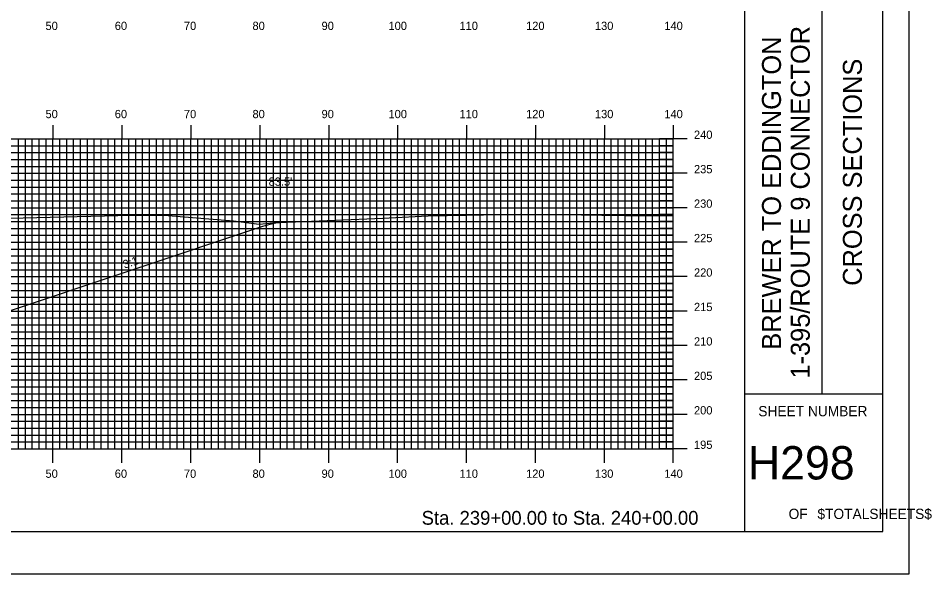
# Model space of a CAD drawing. Extents: x 1801536 to 1801879, y 442591 to 442811.
# Drawn here: x 1801746.5 to 1801879.1, y 442590.5 to 442671.2 of the extents above; entities that cross this region are included whole.
import ezdxf

# ---------------------------------------------------------------- set-up
doc = ezdxf.new("R2010")
doc.units = 0
for name, color, linetype in [('ANNOTATION', 7, 'Continuous'), ('BORDER', 7, 'Continuous'), ('D_Roadway_SlopeLines', 7, 'Continuous'), ('D_Text_Standard', 7, 'Continuous'), ('H_V ANNOTATION', 7, 'Continuous'), ('M_Roadway_Centerline', 7, 'Continuous'), ('MAJOR', 7, 'Continuous'), ('MINOR', 7, 'Continuous'), ('PLOT BOUNDARY', 7, 'Continuous'), ('S_Roadway_Centerline', 7, 'Continuous')]:
    doc.layers.add(name, color=color, linetype=linetype)

msp = doc.modelspace()

# ---------------------------------------------------------------- linework, layer by layer
at = {"layer": 'BORDER'}
for p, q in [((1801851.98, 442596.67), (1801851.98, 442806.67)), ((1801863.16, 442616.67), (1801863.16, 442686.67)), ((1801851.98, 442616.67), (1801871.98, 442616.67))]:
    msp.add_line(p, q, dxfattribs=at)
msp.add_lwpolyline([(1801551.98, 442596.67), (1801871.98, 442596.67), (1801871.98, 442806.67), (1801551.98, 442806.67)], close=True, dxfattribs=at)
at = {"layer": 'D_Roadway_SlopeLines'}
msp.add_line((1801781.97, 442640.93), (1801744.36, 442628.39), dxfattribs=at)
msp.add_arc((1801786.17, 442628.31), 13.3, 94.7119, 108.4349, dxfattribs=at)
at = {"layer": 'MAJOR'}
for p, q in [((1801751.58, 442655.67), (1801751.58, 442653.67)), ((1801761.58, 442655.67), (1801761.58, 442653.67)), ((1801771.58, 442655.67), (1801771.58, 442653.67)), ((1801781.58, 442655.67), (1801781.58, 442653.67)), ((1801791.58, 442655.67), (1801791.58, 442653.67)), ((1801801.58, 442655.67), (1801801.58, 442653.67)), ((1801811.58, 442655.67), (1801811.58, 442653.67)), ((1801821.58, 442655.67), (1801821.58, 442653.67)), ((1801831.58, 442655.67), (1801831.58, 442653.67)), ((1801841.58, 442655.67), (1801841.58, 442653.67)), ((1801561.58, 442653.67), (1801841.58, 442653.67)), ((1801561.58, 442653.67), (1801841.58, 442653.67)), ((1801751.58, 442608.67), (1801751.58, 442653.67)), ((1801761.58, 442608.67), (1801761.58, 442653.67)), ((1801771.58, 442608.67), (1801771.58, 442653.67)), ((1801781.58, 442608.67), (1801781.58, 442653.67)), ((1801791.58, 442608.67), (1801791.58, 442653.67)), ((1801801.58, 442608.67), (1801801.58, 442653.67)), ((1801811.58, 442608.67), (1801811.58, 442653.67)), ((1801821.58, 442608.67), (1801821.58, 442653.67)), ((1801831.58, 442608.67), (1801831.58, 442653.67)), ((1801843.58, 442653.67), (1801839.57, 442653.67)), ((1801841.58, 442608.67), (1801841.58, 442653.67)), ((1801841.58, 442608.67), (1801841.58, 442653.67)), ((1801561.58, 442648.67), (1801841.58, 442648.67)), ((1801843.58, 442648.67), (1801839.57, 442648.67)), ((1801561.58, 442643.67), (1801841.58, 442643.67)), ((1801843.58, 442643.67), (1801839.57, 442643.67)), ((1801561.58, 442638.67), (1801841.58, 442638.67)), ((1801843.58, 442638.67), (1801839.57, 442638.67)), ((1801561.58, 442633.67), (1801841.58, 442633.67)), ((1801843.58, 442633.67), (1801839.57, 442633.67)), ((1801561.58, 442628.67), (1801841.58, 442628.67)), ((1801843.58, 442628.67), (1801839.57, 442628.67)), ((1801561.58, 442623.67), (1801841.58, 442623.67)), ((1801843.58, 442623.67), (1801839.57, 442623.67)), ((1801561.58, 442618.67), (1801841.58, 442618.67)), ((1801843.58, 442618.67), (1801839.57, 442618.67)), ((1801561.58, 442613.67), (1801841.58, 442613.67)), ((1801843.58, 442613.67), (1801839.57, 442613.67)), ((1801561.58, 442608.67), (1801841.58, 442608.67)), ((1801561.58, 442608.67), (1801841.58, 442608.67)), ((1801751.58, 442606.66), (1801751.58, 442608.67)), ((1801761.58, 442606.66), (1801761.58, 442608.67)), ((1801771.58, 442606.66), (1801771.58, 442608.67)), ((1801781.58, 442606.66), (1801781.58, 442608.67)), ((1801791.58, 442606.66), (1801791.58, 442608.67)), ((1801801.58, 442606.66), (1801801.58, 442608.67)), ((1801811.58, 442606.66), (1801811.58, 442608.67)), ((1801821.58, 442606.66), (1801821.58, 442608.67)), ((1801831.58, 442606.66), (1801831.58, 442608.67)), ((1801843.58, 442608.67), (1801839.57, 442608.67)), ((1801841.58, 442606.66), (1801841.58, 442608.67))]:
    msp.add_line(p, q, dxfattribs=at)
at = {"layer": 'MINOR'}
for p, q in [((1801561.58, 442652.67), (1801841.58, 442652.67)), ((1801746.58, 442608.67), (1801746.58, 442653.67)), ((1801747.58, 442608.67), (1801747.58, 442653.67)), ((1801748.58, 442608.67), (1801748.58, 442653.67)), ((1801749.58, 442608.67), (1801749.58, 442653.67)), ((1801750.58, 442608.67), (1801750.58, 442653.67)), ((1801752.58, 442608.67), (1801752.58, 442653.67)), ((1801753.58, 442608.67), (1801753.58, 442653.67)), ((1801754.58, 442608.67), (1801754.58, 442653.67)), ((1801755.58, 442608.67), (1801755.58, 442653.67)), ((1801756.58, 442608.67), (1801756.58, 442653.67)), ((1801757.58, 442608.67), (1801757.58, 442653.67)), ((1801758.58, 442608.67), (1801758.58, 442653.67)), ((1801759.58, 442608.67), (1801759.58, 442653.67)), ((1801760.58, 442608.67), (1801760.58, 442653.67)), ((1801762.58, 442608.67), (1801762.58, 442653.67)), ((1801763.58, 442608.67), (1801763.58, 442653.67)), ((1801764.58, 442608.67), (1801764.58, 442653.67)), ((1801765.58, 442608.67), (1801765.58, 442653.67)), ((1801766.58, 442608.67), (1801766.58, 442653.67)), ((1801767.58, 442608.67), (1801767.58, 442653.67)), ((1801768.58, 442608.67), (1801768.58, 442653.67)), ((1801769.58, 442608.67), (1801769.58, 442653.67)), ((1801770.58, 442608.67), (1801770.58, 442653.67)), ((1801772.58, 442608.67), (1801772.58, 442653.67)), ((1801773.58, 442608.67), (1801773.58, 442653.67)), ((1801774.58, 442608.67), (1801774.58, 442653.67)), ((1801775.58, 442608.67), (1801775.58, 442653.67)), ((1801776.58, 442608.67), (1801776.58, 442653.67)), ((1801777.58, 442608.67), (1801777.58, 442653.67)), ((1801778.58, 442608.67), (1801778.58, 442653.67)), ((1801779.58, 442608.67), (1801779.58, 442653.67)), ((1801780.58, 442608.67), (1801780.58, 442653.67)), ((1801782.58, 442608.67), (1801782.58, 442653.67)), ((1801783.58, 442608.67), (1801783.58, 442653.67)), ((1801784.58, 442608.67), (1801784.58, 442653.67)), ((1801785.58, 442608.67), (1801785.58, 442653.67)), ((1801786.58, 442608.67), (1801786.58, 442653.67)), ((1801787.58, 442608.67), (1801787.58, 442653.67)), ((1801788.58, 442608.67), (1801788.58, 442653.67)), ((1801789.58, 442608.67), (1801789.58, 442653.67)), ((1801790.58, 442608.67), (1801790.58, 442653.67)), ((1801792.58, 442608.67), (1801792.58, 442653.67)), ((1801793.58, 442608.67), (1801793.58, 442653.67)), ((1801794.58, 442608.67), (1801794.58, 442653.67)), ((1801795.58, 442608.67), (1801795.58, 442653.67)), ((1801796.58, 442608.67), (1801796.58, 442653.67)), ((1801797.58, 442608.67), (1801797.58, 442653.67)), ((1801798.58, 442608.67), (1801798.58, 442653.67)), ((1801799.58, 442608.67), (1801799.58, 442653.67)), ((1801800.58, 442608.67), (1801800.58, 442653.67)), ((1801802.58, 442608.67), (1801802.58, 442653.67)), ((1801803.58, 442608.67), (1801803.58, 442653.67)), ((1801804.58, 442608.67), (1801804.58, 442653.67)), ((1801805.58, 442608.67), (1801805.58, 442653.67)), ((1801806.58, 442608.67), (1801806.58, 442653.67)), ((1801807.58, 442608.67), (1801807.58, 442653.67)), ((1801808.58, 442608.67), (1801808.58, 442653.67)), ((1801809.58, 442608.67), (1801809.58, 442653.67)), ((1801810.58, 442608.67), (1801810.58, 442653.67)), ((1801812.58, 442608.67), (1801812.58, 442653.67)), ((1801813.58, 442608.67), (1801813.58, 442653.67)), ((1801814.58, 442608.67), (1801814.58, 442653.67)), ((1801815.58, 442608.67), (1801815.58, 442653.67)), ((1801816.58, 442608.67), (1801816.58, 442653.67)), ((1801817.58, 442608.67), (1801817.58, 442653.67)), ((1801818.58, 442608.67), (1801818.58, 442653.67)), ((1801819.58, 442608.67), (1801819.58, 442653.67)), ((1801820.58, 442608.67), (1801820.58, 442653.67)), ((1801822.58, 442608.67), (1801822.58, 442653.67)), ((1801823.58, 442608.67), (1801823.58, 442653.67)), ((1801824.58, 442608.67), (1801824.58, 442653.67)), ((1801825.58, 442608.67), (1801825.58, 442653.67)), ((1801826.58, 442608.67), (1801826.58, 442653.67)), ((1801827.58, 442608.67), (1801827.58, 442653.67)), ((1801828.58, 442608.67), (1801828.58, 442653.67)), ((1801829.58, 442608.67), (1801829.58, 442653.67)), ((1801830.58, 442608.67), (1801830.58, 442653.67)), ((1801832.58, 442608.67), (1801832.58, 442653.67)), ((1801833.58, 442608.67), (1801833.58, 442653.67)), ((1801834.58, 442608.67), (1801834.58, 442653.67)), ((1801835.58, 442608.67), (1801835.58, 442653.67)), ((1801836.58, 442608.67), (1801836.58, 442653.67)), ((1801837.58, 442608.67), (1801837.58, 442653.67)), ((1801838.58, 442608.67), (1801838.58, 442653.67)), ((1801841.58, 442652.67), (1801839.57, 442652.67)), ((1801839.58, 442608.67), (1801839.58, 442653.67)), ((1801840.58, 442608.67), (1801840.58, 442653.67)), ((1801561.58, 442651.67), (1801841.58, 442651.67)), ((1801841.58, 442651.67), (1801839.57, 442651.67)), ((1801561.58, 442650.67), (1801841.58, 442650.67)), ((1801841.58, 442650.67), (1801839.57, 442650.67)), ((1801561.58, 442649.67), (1801841.58, 442649.67)), ((1801841.58, 442649.67), (1801839.57, 442649.67)), ((1801561.58, 442647.67), (1801841.58, 442647.67)), ((1801841.58, 442647.67), (1801839.57, 442647.67)), ((1801561.58, 442646.67), (1801841.58, 442646.67)), ((1801841.58, 442646.67), (1801839.57, 442646.67)), ((1801561.58, 442645.67), (1801841.58, 442645.67)), ((1801841.58, 442645.67), (1801839.57, 442645.67)), ((1801561.58, 442644.67), (1801841.58, 442644.67)), ((1801841.58, 442644.67), (1801839.57, 442644.67)), ((1801561.58, 442642.67), (1801841.58, 442642.67)), ((1801841.58, 442642.67), (1801839.57, 442642.67)), ((1801561.58, 442641.67), (1801841.58, 442641.67)), ((1801841.58, 442641.67), (1801839.57, 442641.67)), ((1801561.58, 442640.67), (1801841.58, 442640.67)), ((1801561.58, 442639.67), (1801841.58, 442639.67)), ((1801841.58, 442640.67), (1801839.57, 442640.67)), ((1801841.58, 442639.67), (1801839.57, 442639.67)), ((1801561.58, 442637.67), (1801841.58, 442637.67)), ((1801841.58, 442637.67), (1801839.57, 442637.67)), ((1801561.58, 442636.67), (1801841.58, 442636.67)), ((1801561.58, 442635.67), (1801841.58, 442635.67)), ((1801841.58, 442636.67), (1801839.57, 442636.67)), ((1801841.58, 442635.67), (1801839.57, 442635.67)), ((1801561.58, 442634.67), (1801841.58, 442634.67)), ((1801841.58, 442634.67), (1801839.57, 442634.67)), ((1801561.58, 442632.67), (1801841.58, 442632.67)), ((1801561.58, 442631.67), (1801841.58, 442631.67)), ((1801841.58, 442632.67), (1801839.57, 442632.67)), ((1801841.58, 442631.67), (1801839.57, 442631.67)), ((1801561.58, 442630.67), (1801841.58, 442630.67)), ((1801841.58, 442630.67), (1801839.57, 442630.67)), ((1801561.58, 442629.67), (1801841.58, 442629.67)), ((1801841.58, 442629.67), (1801839.57, 442629.67)), ((1801561.58, 442627.67), (1801841.58, 442627.67)), ((1801841.58, 442627.67), (1801839.57, 442627.67)), ((1801561.58, 442626.67), (1801841.58, 442626.67)), ((1801841.58, 442626.67), (1801839.57, 442626.67)), ((1801561.58, 442625.67), (1801841.58, 442625.67)), ((1801841.58, 442625.67), (1801839.57, 442625.67)), ((1801561.58, 442624.67), (1801841.58, 442624.67)), ((1801841.58, 442624.67), (1801839.57, 442624.67)), ((1801561.58, 442622.67), (1801841.58, 442622.67)), ((1801841.58, 442622.67), (1801839.57, 442622.67)), ((1801561.58, 442621.67), (1801841.58, 442621.67)), ((1801841.58, 442621.67), (1801839.57, 442621.67)), ((1801561.58, 442620.67), (1801841.58, 442620.67)), ((1801561.58, 442619.67), (1801841.58, 442619.67)), ((1801841.58, 442620.67), (1801839.57, 442620.67)), ((1801841.58, 442619.67), (1801839.57, 442619.67)), ((1801561.58, 442617.67), (1801841.58, 442617.67)), ((1801841.58, 442617.67), (1801839.57, 442617.67)), ((1801561.58, 442616.67), (1801841.58, 442616.67)), ((1801561.58, 442615.67), (1801841.58, 442615.67)), ((1801841.58, 442616.67), (1801839.57, 442616.67)), ((1801841.58, 442615.67), (1801839.57, 442615.67)), ((1801561.58, 442614.67), (1801841.58, 442614.67)), ((1801841.58, 442614.67), (1801839.57, 442614.67)), ((1801561.58, 442612.67), (1801841.58, 442612.67)), ((1801561.58, 442611.67), (1801841.58, 442611.67)), ((1801841.58, 442612.67), (1801839.57, 442612.67)), ((1801841.58, 442611.67), (1801839.57, 442611.67)), ((1801561.58, 442610.67), (1801841.58, 442610.67)), ((1801841.58, 442610.67), (1801839.57, 442610.67)), ((1801561.58, 442609.67), (1801841.58, 442609.67)), ((1801841.58, 442609.67), (1801839.57, 442609.67))]:
    msp.add_line(p, q, dxfattribs=at)
at = {"layer": 'PLOT BOUNDARY'}
msp.add_lwpolyline([(1801535.79, 442590.55), (1801875.79, 442590.55), (1801875.79, 442810.55), (1801535.79, 442810.55)], close=True, dxfattribs=at)
at = {"layer": 'S_Roadway_Centerline'}
msp.add_lwpolyline([(1801743.29, 442642.13), (1801757.07, 442642.43), (1801762.98, 442642.59), (1801768.31, 442642.54), (1801769.47, 442642.47), (1801777.79, 442641.76), (1801781.51, 442641.28), (1801783.55, 442641.48), (1801785.63, 442641.6), (1801799.44, 442642.17), (1801806.92, 442642.52), (1801807.75, 442642.54), (1801808.76, 442642.56), (1801819.35, 442642.76), (1801828.26, 442642.63), (1801831.23, 442642.59), (1801834.68, 442642.54), (1801841.58, 442642.52)], dxfattribs=at)

# ---------------------------------------------------------------- texts
at = {"layer": 'ANNOTATION'}
msp.add_text('3:1', height=1.2, rotation=18.4349, dxfattribs=at).set_placement((1801761.96, 442634.82))
at = {"layer": 'BORDER'}
for s, p in [('1-395/ROUTE 9 CONNECTOR', (1801861.38, 442618.87)), ('BREWER TO EDDINGTON', (1801857.2, 442623.07)), ('CROSS SECTIONS', (1801868.94, 442632.34))]:
    msp.add_text(s, height=2.7557, rotation=90, dxfattribs=at).set_placement(p)
for s, height, p in [('SHEET NUMBER', 1.4905, (1801853.91, 442613.4)), ('H298', 4.839, (1801852.41, 442604.23)), ('OF', 1.491, (1801858.31, 442598.49)), ('$TOTALSHEETS$', 1.4905, (1801862.49, 442598.49))]:
    msp.add_text(s, height=height, dxfattribs=at).set_placement(p)
at = {"layer": 'D_Text_Standard'}
msp.add_text("83.5'", height=1.2, dxfattribs=at).set_placement((1801782.87, 442646.86))
at = {"layer": 'H_V ANNOTATION'}
for s, height, p in [('50', 1.2, (1801750.5, 442669.47)), ('60', 1.2, (1801760.55, 442669.47)), ('70', 1.2, (1801770.58, 442669.47)), ('80', 1.2, (1801780.53, 442669.47)), ('90', 1.2, (1801790.55, 442669.47)), ('100', 1.2, (1801800.26, 442669.47)), ('110', 1.2, (1801810.56, 442669.47)), ('120', 1.2, (1801820.22, 442669.47)), ('130', 1.2, (1801830.21, 442669.47)), ('140', 1.2, (1801840.28, 442669.47)), ('50', 1.2, (1801750.5, 442656.67)), ('60', 1.2, (1801760.55, 442656.67)), ('70', 1.2, (1801770.58, 442656.67)), ('80', 1.2, (1801780.53, 442656.67)), ('90', 1.2, (1801790.55, 442656.67)), ('100', 1.2, (1801800.26, 442656.67)), ('110', 1.2, (1801810.56, 442656.67)), ('120', 1.2, (1801820.22, 442656.67)), ('130', 1.2, (1801830.21, 442656.67)), ('140', 1.2, (1801840.28, 442656.67)), ('240', 1.2, (1801844.58, 442653.67)), ('235', 1.2, (1801844.58, 442648.67)), ('230', 1.2, (1801844.58, 442643.67)), ('225', 1.2, (1801844.58, 442638.67)), ('220', 1.2, (1801844.58, 442633.67)), ('215', 1.2, (1801844.58, 442628.67)), ('210', 1.2, (1801844.58, 442623.67)), ('205', 1.2, (1801844.58, 442618.67)), ('200', 1.2, (1801844.58, 442613.67)), ('195', 1.2, (1801844.58, 442608.67)), ('50', 1.2, (1801750.5, 442604.47)), ('60', 1.2, (1801760.55, 442604.47)), ('70', 1.2, (1801770.58, 442604.47)), ('80', 1.2, (1801780.53, 442604.47)), ('90', 1.2, (1801790.55, 442604.47)), ('100', 1.2, (1801800.26, 442604.47)), ('110', 1.2, (1801810.56, 442604.47)), ('120', 1.2, (1801820.22, 442604.47)), ('130', 1.2, (1801830.21, 442604.47)), ('140', 1.2, (1801840.28, 442604.47)), ('Sta. 239+00.00 to Sta. 240+00.00', 2.0004, (1801805.07, 442597.66))]:
    msp.add_text(s, height=height, dxfattribs=at).set_placement(p)
at = {"layer": 'M_Roadway_Centerline'}
for s, p in [('C', (1801768.3, 442642.54)), ('L', (1801768.31, 442642.53))]:
    msp.add_text(s, height=0.0146, dxfattribs=at).set_placement(p)

doc.saveas('drawing.dxf')
